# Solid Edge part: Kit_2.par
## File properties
Last saved by: psaghy
Revision: 78
Sűrűség: 0,000 kg/m^3
Pontosság: 0,990
Dokumentum tartalom típus: 0
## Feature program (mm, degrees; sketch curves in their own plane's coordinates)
base feature "unnamed BaseFeature 1"
sketch for "Furat_2" plane through (0, -3.875, 7) normal (0, 0, 1) x-axis (0, 1, 0)
  hole centre (-0.625, 0) bore radius 2.067
hole "Furat_2" nominal diameter 5 finite  ThreadDepth = 4.5 mm
sketch for "Kihúzás_1" #1 plane through (0, 12.5, 0) normal (0, 1, 0) x-axis (0, 0, -1)
  arc centre (0, 0) radius 6 from (4.4721, -4) to (-4.4721, -4) cw
  line (-4.4721, -4) -> (4.4721, -4)
sketch for "Kihúzás_1" #2 plane through (0, 12.5, 0) normal (0, 1, 0) x-axis (0, 0, -1)
  line (-4.4721, 4) -> (4.4721, 4)
extrude "Kihúzás_1" add finite 8.92 along -normal
thread "unnamed Thread 1"
chamfer "Letörés_1" setback 1
sketch for "Kivágás_1" #1 plane through (0, 12.5, 0) normal (0, 1, 0) x-axis (0, 0, -1)
  line (-4.4721, -4) -> (4.4721, -4)
  arc centre (0, 0) radius 6 from (4.4721, -4) to (-4.4721, -4) cw
sketch for "Kivágás_1" #2 plane through (0, 12.5, 0) normal (0, 1, 0) x-axis (0, 0, -1)
  line (-4.4721, 4) -> (4.4721, 4)
extrude "Kivágás_1" cut finite 9.92 along -normal
chamfer "Letörés_2" setback 0.5
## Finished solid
Body 1: solid body, 32 faces, 71 edges, 40 vertices.
  Faces by surface: plane 13, cylinder 11, cone 8
  Edges by curve: line 32, circle 31, intersection 4, spline 4
Bounding box of the edges (mm): 16.000 x 22.250 x 15.000, from (-8, -9.75, -8) to (8, 12.5, 7).
Cylindrical faces by radius (mm): R2 x1, R2.06 x1, R2.067 x1, R5 x2, R5.6 x1, R6 x4, R8 x1
Conical faces (half-angle, radius in mm at the cone's reference point): 45 deg R2.1 x2, 45 deg R2.567 x1, 45 deg R6 x2, 59 deg R1.0335 x1, 60 deg R5.5 x2
Planar faces by outward normal: +x 1, +y 7, +z 2, -x 1, -y 2
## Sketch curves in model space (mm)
arc centre (0, 12.5, 0) radius 6 from (4, 12.5, -4.4721) through (5.9975, 12.5, 0.174) to (4, 12.5, 4.4721)
line (4, 12.5, 4.4721) -> (4, 12.5, -4.4721)
arc centre (0, 12.5, 0) radius 6 from (-4, 12.5, 4.4721) through (-5.9975, 12.5, -0.174) to (-4, 12.5, -4.4721)
line (-4, 12.5, 4.4721) -> (-4, 12.5, -4.4721)
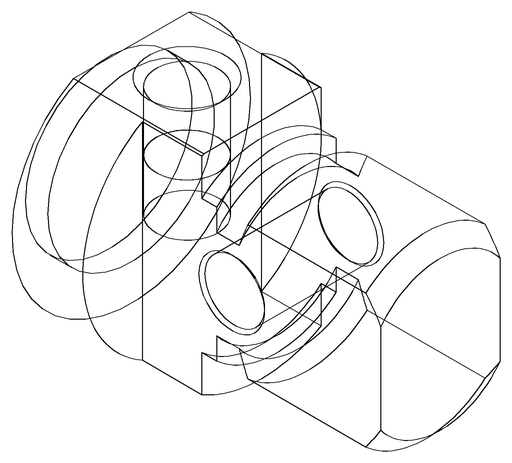
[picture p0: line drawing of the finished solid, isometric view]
